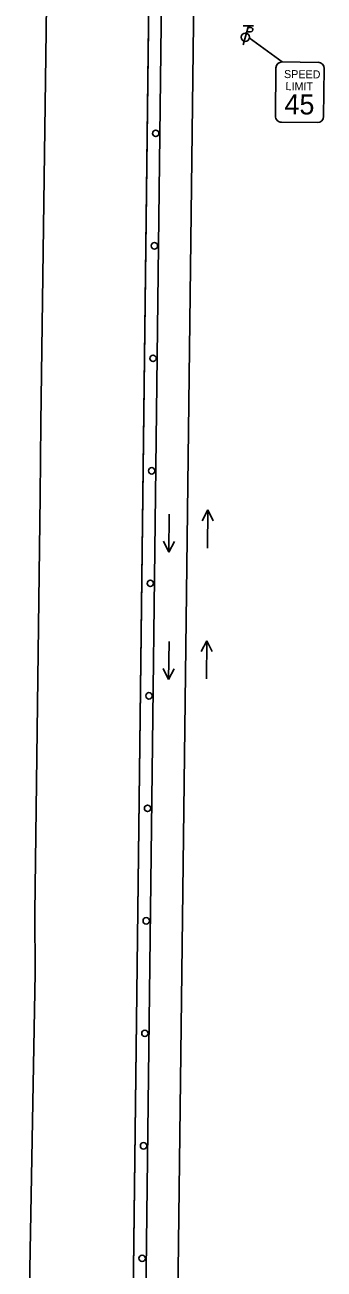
# Model space of a CAD drawing. Extents: x 1651568 to 1653044, y 601329 to 611807.
# Drawn here: x 1652520.5 to 1652613.7, y 607405.3 to 607792.4 of the extents above; entities that cross this region are included whole.
import ezdxf

# ---------------------------------------------------------------- set-up
doc = ezdxf.new("R2010")
doc.units = 0
for name, color, linetype in [('CM_Corridor_Design', 7, 'Continuous'), ('DT_X_Break_Line', 7, 'Continuous'), ('DT_X_Contour_Major', 7, 'Continuous'), ('MD_P_Drive_MatchLine', 7, 'Continuous'), ('MD_P_Intersection_MatchLine', 7, 'Continuous'), ('PF_X_Ground_Line', 7, 'Continuous'), ('PV_P_EOP', 7, 'Continuous'), ('PV_X_EOP', 7, 'Continuous')]:
    doc.layers.add(name, color=color, linetype=linetype)

msp = doc.modelspace()

# ---------------------------------------------------------------- linework, layer by layer
at = {"layer": 'CM_Corridor_Design'}
for p, q in [((1652577.42, 607641.48), (1652575.66, 607638.13)), ((1652577.42, 607641.48), (1652577.29, 607629.62)), ((1652577.42, 607641.48), (1652579.11, 607638.09)), ((1652565.28, 607628.35), (1652565.41, 607640.21)), ((1652565.28, 607628.35), (1652563.59, 607631.74)), ((1652565.28, 607628.35), (1652567.04, 607631.7)), ((1652565.24, 607588.72), (1652565.37, 607600.58)), ((1652577.12, 607600.8), (1652575.36, 607597.45)), ((1652577.12, 607600.8), (1652576.99, 607588.95)), ((1652577.12, 607600.8), (1652578.81, 607597.41)), ((1652565.24, 607588.72), (1652563.55, 607592.11)), ((1652565.24, 607588.72), (1652567, 607592.07))]:
    msp.add_line(p, q, dxfattribs=at)
at = {"layer": 'DT_X_Break_Line'}
for centre in [(1652561.22, 607758.64), (1652560.8, 607723.64), (1652560.38, 607688.64), (1652559.95, 607653.65), (1652559.53, 607618.65), (1652559.11, 607583.65), (1652558.68, 607548.65), (1652558.26, 607513.66), (1652557.84, 607478.66), (1652557.42, 607443.66), (1652556.99, 607408.66)]:
    msp.add_circle(centre, 1, dxfattribs=at)
at = {"layer": 'DT_X_Contour_Major'}
msp.add_line((1652551.76, 607199.34), (1652567.38, 608491.59), dxfattribs=at)
for points in [[(1652520.46, 607301.97), (1652521.05, 607315.67), (1652521.05, 607315.61), (1652521.06, 607315.89), (1652521.05, 607315.67), (1652522.05, 607405.28), (1652522.05, 607405.32), (1652523.62, 607497.33), (1652523.6, 607516.01), (1652525.27, 607645.77), (1652525.48, 607668.54), (1652527.11, 607790.41), (1652527.11, 607790.42), (1652529.48, 607988.14), (1652531.24, 608129.69), (1652532.94, 608285.66), (1652534.22, 608392.25), (1652536.08, 608599.02), (1652568.71, 608598.61), (1652551.76, 607199.34), (1652540.01, 606229.06)], [(1652520.46, 607301.97), (1652521.05, 607315.67), (1652521.05, 607315.61), (1652521.06, 607315.89), (1652521.05, 607315.67), (1652522.05, 607405.28), (1652522.05, 607405.32), (1652523.62, 607497.33), (1652523.6, 607516.01), (1652525.27, 607645.77), (1652525.48, 607668.54), (1652527.11, 607790.41), (1652527.11, 607790.42), (1652529.48, 607988.14), (1652531.24, 608129.69), (1652532.94, 608285.66), (1652534.22, 608392.25), (1652536.08, 608599.02), (1652568.71, 608598.61), (1652551.76, 607199.34), (1652540.01, 606229.06)], [(1652527.11, 607790.41), (1652529.48, 607988.14), (1652531.24, 608129.69), (1652532.94, 608285.66), (1652534.22, 608392.25), (1652535.14, 608525.89)], [(1652522.05, 607405.32), (1652523.62, 607497.33), (1652523.6, 607516.01), (1652525.27, 607645.77), (1652525.48, 607668.54), (1652527.11, 607790.42)]]:
    msp.add_lwpolyline(points, dxfattribs=at)
at = {"layer": 'MD_P_Drive_MatchLine'}
msp.add_line((1652590.32, 607788.35), (1652600.56, 607780.86), dxfattribs=at)
at = {"layer": 'MD_P_Intersection_MatchLine'}
for p, q in [((1652591.67, 607792.14), (1652588.47, 607792.14)), ((1652590.07, 607792.14), (1652588.47, 607786.14)), ((1652589.91, 607791.54), (1652590.76, 607791.54)), ((1652589.57, 607790.26), (1652590.76, 607790.26))]:
    msp.add_line(p, q, dxfattribs=at)
msp.add_circle((1652589.11, 607788.54), 1.3, dxfattribs=at)
msp.add_arc((1652590.78, 607790.9), 0.638, 268.8767, 91.1233, dxfattribs=at)
at = {"layer": 'PF_X_Ground_Line'}
for points in [[(1652611.81, 607780.73), (1652600.56, 607780.86)], [(1652598.66, 607779), (1652598.5, 607764)], [(1652613.5, 607763.84), (1652613.66, 607778.84)], [(1652600.35, 607762.11), (1652611.6, 607761.98)]]:
    msp.add_lwpolyline(points, dxfattribs=at)
for centre, start, end in [((1652600.54, 607778.98), 89.3709, 179.3709), ((1652611.79, 607778.86), 359.3709, 89.3709), ((1652600.37, 607763.98), 179.3709, 269.3709), ((1652611.62, 607763.86), 269.3709, 359.3709)]:
    msp.add_arc(centre, 1.88, start, end, dxfattribs=at)
at = {"layer": 'PV_P_EOP'}
msp.add_line((1652556.99, 607300.84), (1652572.67, 608598.56), dxfattribs=at)
at = {"layer": 'PV_X_EOP'}
msp.add_line((1652566.99, 607300.72), (1652582.67, 608598.44), dxfattribs=at)

# ---------------------------------------------------------------- texts
at = {"layer": 'PF_X_Ground_Line'}
for s, height, p in [('SPEED', 2.5, (1652601.16, 607775.85)), ('LIMIT', 2.5, (1652601.64, 607772.09)), ('45', 6.25, (1652601.3, 607764.6))]:
    msp.add_text(s, height=height, rotation=359.3709, dxfattribs=at).set_placement(p)

doc.saveas('drawing.dxf')
